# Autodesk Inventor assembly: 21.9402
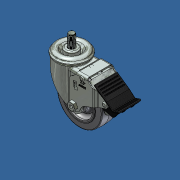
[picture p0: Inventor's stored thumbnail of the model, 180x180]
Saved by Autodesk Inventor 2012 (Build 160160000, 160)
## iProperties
Created: 2010-10
Part Number: 21.9402
Document SubType Name: Assembly
Designer: Administrator
Description: 3.5 CASTER W/BRAKE
Translation Standard: STEP AP214IS
FileName: Colson-2.03256.445 BRK5 .step.step
PreProcessor: SolidWorks 2010
PostProcessor: Build: 236a, Release: 2009 RTM - Date: Fri 02/22/2008
Sent Units: Inches
Uncertainty: 1e-05
Author: Administrator
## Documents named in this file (3)
- C:\Andys Backup Data\ANDY'S INVENTOR\INVENTOR LIBRARIES\PARTS LIBRARY\FEET WHEELS FLOOR FASTENING SUPPORTS\21.9402 CASTER 3.5 BRK.iam
- C:\Andys Backup Data\ANDY'S INVENTOR\INVENTOR LIBRARIES\PARTS LIBRARY\FASTENING ELEMENTS\SCREWS CAP\21.1257 M12X40.ipt
- C:\Andys Backup Data\ANDY'S INVENTOR\INVENTOR LIBRARIES\PARTS LIBRARY\FEET WHEELS FLOOR FASTENING SUPPORTS\SUBCOMPONENTS\21.9402_1 CASTER 3.5 BRK.iam
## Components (2 placed, 2 different names)
1. 21.9402_1 CASTER 3.5 BRK:1 [sub-assembly] — Insert:1
2. 21.1257 M12X40:1 — Insert:1
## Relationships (1: Insert 1)
- Insert:1: 21.9402_1 CASTER 3.5 BRK:1 ↔ 21.1257 M12X40:1
